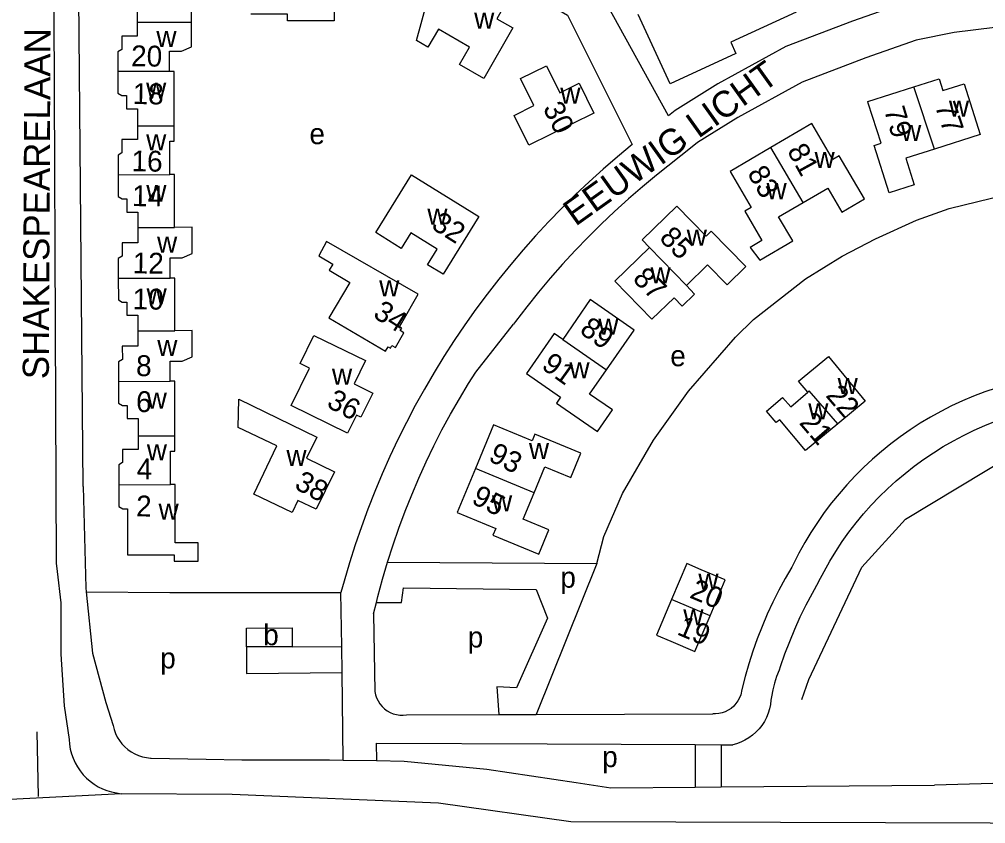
# Model space of a CAD drawing. Extents: x 159441 to 162086, y 388175 to 389787.
# Drawn here: x 161032.2 to 161217.5, y 388347.8 to 388501.9 of the extents above; entities that cross this region are included whole.
import ezdxf

# ---------------------------------------------------------------- set-up
doc = ezdxf.new("R2010")
doc.units = 0
for name, color, linetype in [('BLT_Basislijn', 7, 'Continuous'), ('BLT_Bebouwing', 7, 'Continuous'), ('BLT_Centroide', 7, 'Continuous'), ('BLT_Huisnummer', 7, 'Continuous'), ('BLT_Huisnummer_ tussenligend', 7, 'Continuous'), ('BLT_Onderverdeling_panden', 7, 'Continuous'), ('BLT_Straatnaam', 7, 'Continuous'), ('BLT_Vlakafsluiter', 7, 'Continuous')]:
    doc.layers.add(name, color=color, linetype=linetype)

msp = doc.modelspace()

# ---------------------------------------------------------------- linework, layer by layer
at = {"layer": 'BLT_Basislijn'}
for p, q in [((161044.45, 388412.36), (161043.5, 388520.52)), ((161156.97, 388489.54), (161150.84, 388502.85)), ((161181.14, 388503.3), (161168.61, 388497.54)), ((161168.61, 388497.54), (161169.61, 388495.36)), ((161169.61, 388495.36), (161156.97, 388489.54)), ((161161.23, 388477.48), (161154.41, 388472.07)), ((161119.72, 388434.3), (161126.93, 388443.46)), ((161102.8, 388397.85), (161142.94, 388397.62)), ((161142.94, 388397.62), (161131.31, 388368.69)), ((161045.04, 388392.19), (161061.04, 388392.06)), ((161061.04, 388392.06), (161068.06, 388392.06)), ((161068.06, 388392.06), (161093.88, 388392.06)), ((161094.02, 388381.72), (161093.88, 388392.06)), ((161100.15, 388387.99), (161100.67, 388390.13)), ((161100.15, 388387.99), (161100.38, 388373.11)), ((161075.75, 388381.62), (161075.75, 388376.55)), ((161084.54, 388381.63), (161094.02, 388381.72)), ((161094.08, 388376.72), (161094.02, 388381.72)), ((161075.75, 388376.55), (161094.08, 388376.72)), ((161094.29, 388359.95), (161094.08, 388376.72)), ((161106.47, 388368.61), (161124.14, 388368.67)), ((161124.14, 388368.67), (161131.31, 388368.69)), ((161131.31, 388368.69), (161165.19, 388368.78)), ((161035.9, 388352.97), (161035.64, 388365.37)), ((161100.63, 388363.17), (161100.72, 388359.84)), ((161100.63, 388363.17), (161133.4, 388363.02)), ((161133.4, 388363.02), (161161.8, 388362.9)), ((161161.8, 388362.9), (161166.8, 388362.88)), ((161161.8, 388362.9), (161161.8, 388354.77)), ((161166.8, 388362.88), (161166.8, 388354.81)), ((161166.8, 388362.88), (161169.01, 388362.87)), ((161057.5, 388360.31), (161068.06, 388360.12)), ((161094.29, 388359.95), (161100.72, 388359.84)), ((161161.8, 388354.77), (161166.8, 388354.81)), ((161166.8, 388354.81), (161207.68, 388355.15))]:
    msp.add_line(p, q, dxfattribs=at)
for points in [[(161038.68, 388533.55), (161039.27, 388397.68), (161039.46, 388396.05)], [(161106.86, 388520.45), (161137.31, 388502.69), (161149.7, 388477.9)], [(161209.96, 388506.74), (161202.16, 388505.14), (161191.95, 388501.56), (161179.18, 388496.71), (161166.15, 388489.55), (161157.98, 388484.44), (161156.67, 388483.44)], [(161156.67, 388483.44), (161144.86, 388504.81), (161145.34, 388505.05)], [(161252.46, 388501.23), (161231.19, 388501.83), (161211.46, 388499.39)], [(161211.46, 388499.39), (161204.16, 388497.89), (161194.52, 388494.52), (161182.33, 388489.88), (161169.95, 388483.08), (161162.26, 388478.27), (161161.23, 388477.48)], [(161149.7, 388477.9), (161146.9, 388475.58), (161144.14, 388473.21), (161141.45, 388470.77), (161138.8, 388468.27), (161136.21, 388465.72), (161133.68, 388463.11), (161131.2, 388460.44), (161128.79, 388457.72), (161126.43, 388454.95), (161124.14, 388452.13), (161121.91, 388449.25), (161119.74, 388446.33), (161117.64, 388443.36), (161115.6, 388440.35), (161113.63, 388437.29), (161111.73, 388434.19), (161109.89, 388431.05), (161108.13, 388427.87), (161106.43, 388424.65), (161104.81, 388421.4), (161103.26, 388418.11), (161101.78, 388414.78), (161100.38, 388411.43), (161099.05, 388408.04), (161097.79, 388404.63), (161096.61, 388401.19), (161095.51, 388397.72), (161094.48, 388394.23), (161093.88, 388392.06)], [(161154.41, 388472.07), (161151.68, 388469.8), (161148.99, 388467.48), (161146.35, 388465.09), (161143.77, 388462.65), (161141.25, 388460.15), (161138.78, 388457.59), (161136.37, 388454.98), (161134.02, 388452.31), (161131.73, 388449.59), (161129.5, 388446.82), (161127.34, 388444), (161126.93, 388443.46)], [(161142.94, 388397.62), (161144.27, 388402.76), (161147.83, 388411.06), (161153.81, 388421.28), (161160.51, 388430.62), (161169.5, 388441.01), (161173, 388444.35), (161182.93, 388452.15), (161189.95, 388456.49), (161196.34, 388459.87), (161204.24, 388463.4), (161210.47, 388465.66), (161223.83, 388468.92), (161234.58, 388469.87), (161249.06, 388469.87), (161261.63, 388468.97), (161276.91, 388466.53), (161314.68, 388462.2)], [(161102.8, 388397.85), (161103.86, 388401.18), (161104.98, 388404.41), (161106.17, 388407.62), (161107.44, 388410.8), (161108.79, 388413.96), (161110.2, 388417.07), (161111.69, 388420.16), (161113.25, 388423.21), (161114.88, 388426.22), (161116.58, 388429.19), (161118.35, 388432.12), (161119.72, 388434.3)], [(161219.48, 388431.24), (161217.31, 388430.5), (161215.17, 388429.67), (161213.05, 388428.78), (161210.97, 388427.81), (161208.92, 388426.77), (161206.91, 388425.66), (161204.94, 388424.48), (161203.01, 388423.23), (161201.13, 388421.91), (161199.3, 388420.53), (161197.51, 388419.09), (161195.77, 388417.58), (161194.09, 388416.02), (161192.47, 388414.4), (161190.9, 388412.72), (161189.39, 388410.99), (161187.94, 388409.21), (161186.55, 388407.38), (161185.23, 388405.5), (161183.98, 388403.57), (161182.79, 388401.61), (161181.67, 388399.6), (161180.63, 388397.56), (161180.32, 388396.92)], [(161185.47, 388394.09), (161186.5, 388396.08), (161187.59, 388398.03), (161188.75, 388399.93), (161189.98, 388401.8), (161191.28, 388403.61), (161192.64, 388405.39), (161194.06, 388407.11), (161195.55, 388408.78), (161197.09, 388410.39), (161198.69, 388411.95), (161200.35, 388413.45), (161202.05, 388414.89), (161203.81, 388416.27), (161205.62, 388417.59), (161207.47, 388418.84), (161209.36, 388420.02), (161211.3, 388421.13), (161213.27, 388422.17), (161215.29, 388423.15), (161217.33, 388424.05), (161219.41, 388424.87)], [(161182.22, 388371.55), (161183.56, 388375.39), (161193.75, 388396.9), (161202.14, 388406.08), (161222.4, 388418.29), (161232.89, 388422.06), (161242.43, 388423.36), (161250.05, 388422.72), (161287.09, 388418.41), (161290.39, 388417.22), (161292.6, 388414.97), (161293.51, 388411.95), (161294.09, 388393.96)], [(161044.45, 388412.36), (161044.96, 388392.95), (161045.04, 388392.19)], [(161310.31, 388401.34), (161304.94, 388397.76), (161302.38, 388393.16), (161297.78, 388384.47), (161294.21, 388377.06), (161290.88, 388369.39), (161288.33, 388365.05), (161287.82, 388362.74), (161286.54, 388361.21), (161283.21, 388358.4), (161276.57, 388357.63), (161259.19, 388356.61), (161207.68, 388355.15)], [(161100.67, 388390.13), (161100.96, 388391.32), (161101.85, 388394.63), (161102.8, 388397.85)], [(161180.32, 388396.92), (161179.04, 388394.72), (161177.82, 388392.49), (161176.68, 388390.22), (161175.61, 388387.91), (161174.61, 388385.57), (161173.69, 388383.2), (161172.84, 388380.8), (161172.07, 388378.38), (161171.37, 388375.93), (161170.76, 388373.47), (161170.53, 388372.47)], [(161039.46, 388396.05), (161040.17, 388390.05), (161040.17, 388380.22), (161040.82, 388370.32), (161041.76, 388363.9)], [(161185.47, 388394.09), (161184.21, 388391.87), (161183.01, 388389.61), (161181.88, 388387.32), (161180.83, 388384.99), (161179.85, 388382.62), (161178.94, 388380.23), (161178.11, 388377.81), (161177.91, 388377.18)], [(161045.04, 388392.19), (161046.24, 388380.43), (161048.8, 388370.98), (161050.2, 388366.55)], [(161100.67, 388390.13), (161105.48, 388390.16), (161105.89, 388392.94), (161131.32, 388392.61), (161133.46, 388387.14), (161127.56, 388373.78), (161123.79, 388373.95), (161124.14, 388368.67)], [(161177.91, 388377.18), (161177.42, 388375.93), (161177.01, 388374.66), (161176.68, 388373.37), (161176.42, 388372.06), (161176.33, 388371.44)], [(161100.38, 388373.11), (161100.5, 388372.47), (161100.71, 388371.85), (161100.99, 388371.27), (161101.33, 388370.72), (161101.75, 388370.22), (161102.22, 388369.77), (161102.74, 388369.39), (161103.31, 388369.07), (161103.91, 388368.82), (161104.54, 388368.65), (161105.18, 388368.56), (161105.83, 388368.54), (161106.47, 388368.61)], [(161170.53, 388372.47), (161170.3, 388371.86), (161169.99, 388371.29), (161169.62, 388370.76), (161169.18, 388370.28), (161168.69, 388369.85), (161168.15, 388369.49), (161167.57, 388369.2), (161166.96, 388368.98), (161166.33, 388368.84), (161165.68, 388368.78), (161165.19, 388368.78)], [(161176.33, 388371.44), (161176.23, 388370.58), (161176.05, 388369.73), (161175.79, 388368.9), (161175.46, 388368.09), (161175.06, 388367.32), (161174.58, 388366.59), (161174.05, 388365.9), (161173.45, 388365.27), (161172.79, 388364.7), (161172.09, 388364.19), (161171.34, 388363.74), (161170.55, 388363.37), (161169.74, 388363.07), (161169.01, 388362.87)], [(161050.2, 388366.55), (161050.39, 388365.79), (161050.66, 388365.05), (161050.99, 388364.34), (161051.4, 388363.67), (161051.88, 388363.05), (161052.42, 388362.47), (161053.01, 388361.96), (161053.65, 388361.5), (161054.33, 388361.12), (161055.05, 388360.8), (161055.8, 388360.57), (161056.57, 388360.4), (161057.35, 388360.32), (161057.5, 388360.31)], [(161041.76, 388363.9), (161041.83, 388362.97), (161041.98, 388362.06), (161042.21, 388361.16), (161042.51, 388360.29), (161042.89, 388359.44), (161043.34, 388358.63), (161043.86, 388357.86), (161044.45, 388357.14), (161045.09, 388356.48), (161045.79, 388355.87), (161046.53, 388355.32), (161047.33, 388354.84), (161048.16, 388354.43), (161049.02, 388354.09), (161049.91, 388353.83), (161050.82, 388353.65), (161051.74, 388353.47)], [(161068.06, 388360.12), (161074.85, 388360), (161091.71, 388360), (161094.29, 388359.95)], [(161100.72, 388359.84), (161106.01, 388359.74), (161121.85, 388358.21), (161138.96, 388355.66), (161145.61, 388354.63), (161161.8, 388354.77)], [(161300.85, 388350.22), (161285.77, 388350.48), (161269.67, 388349.71), (161253.82, 388348.43), (161238.49, 388347.75), (161137.94, 388348.07), (161112.58, 388351.71), (161072.99, 388353.31), (161051.74, 388353.47)]]:
    msp.add_lwpolyline(points, dxfattribs=at)
at = {"layer": 'BLT_Bebouwing'}
for p, q in [((161054.82, 388501.29), (161054.83, 388500)), ((161184.17, 388481.95), (161176.33, 388477.36)), ((161153.04, 388458.2), (161153.03, 388458.2)), ((161141.69, 388448.18), (161136.39, 388440.54)), ((161123.13, 388424.2), (161119.66, 388415.81)), ((161075.75, 388381.62), (161075.74, 388385.21)), ((161084.54, 388381.63), (161075.75, 388381.62))]:
    msp.add_line(p, q, dxfattribs=at)
for points in [[(161051.06, 388511.52), (161051.07, 388507.53), (161051.82, 388507.09), (161052.72, 388507.09), (161052.72, 388504.57), (161054.82, 388504.58), (161054.82, 388501.29)], [(161065.22, 388501.31), (161065.2, 388506.92), (161063.29, 388507.49), (161061.88, 388507.49), (161061.87, 388511.73), (161060.97, 388511.72)], [(161115.81, 388510.66), (161123.13, 388506.48), (161123.43, 388506.89), (161125.78, 388505.59), (161123.76, 388502.03), (161126.81, 388500.29), (161121.27, 388490.57), (161116.61, 388493.23), (161118.51, 388496.56), (161112.56, 388500), (161110.56, 388496.57), (161108.38, 388497.83), (161110.33, 388505.09), (161113.62, 388504.21), (161114.17, 388505.18), (161113.02, 388505.84), (161115.81, 388510.66)], [(161092.59, 388503.26), (161092.59, 388501.63), (161083.62, 388501.6), (161083.61, 388502.91), (161076.63, 388502.89)], [(161061.02, 388491.93), (161061.01, 388495.79), (161063.31, 388495.79), (161065.23, 388496.65), (161065.22, 388501.31)], [(161054.83, 388500), (161054.83, 388498.66), (161051.84, 388498.66), (161051.84, 388496.12), (161051.1, 388495.67), (161051.11, 388491.9)], [(161051.11, 388491.9), (161051.12, 388487.73), (161051.87, 388487.28), (161052.77, 388487.28), (161052.77, 388484.77), (161054.87, 388484.77), (161054.88, 388481.49)], [(161061.92, 388481.5), (161061.93, 388491.93), (161061.02, 388491.93)], [(161127.07, 388483.5), (161130.87, 388485.37), (161128.3, 388490.58), (161133.26, 388493.02), (161135.82, 388487.81), (161139.56, 388489.65), (161142.37, 388483.95), (161129.88, 388477.79), (161127.07, 388483.5)], [(161203.75, 388489), (161208.57, 388490.53), (161209.3, 388488.27), (161213.34, 388489.55), (161216.42, 388479.81), (161207.66, 388477.02)], [(161207.66, 388477.02), (161202.19, 388475.28), (161203.81, 388470.18), (161199.01, 388468.65), (161196.11, 388477.74), (161197.44, 388478.17), (161194.99, 388485.83), (161194.89, 388486.19), (161203.75, 388489)], [(161054.88, 388481.49), (161054.88, 388478.87), (161051.89, 388478.86), (161051.89, 388476.34), (161051.14, 388475.89), (161051.15, 388472.11)], [(161061.08, 388472.14), (161061.06, 388478.55), (161061.92, 388478.55), (161061.92, 388481.5)], [(161182.49, 388466.82), (161187.2, 388469.57), (161189.9, 388464.95), (161194.25, 388467.5), (161189.43, 388475.75), (161188.21, 388475.04), (161184.17, 388481.95)], [(161176.33, 388477.36), (161168.48, 388472.77), (161172.52, 388465.85), (161171.31, 388465.14), (161174.6, 388459.51), (161172.34, 388458.18), (161174.2, 388455.78), (161180.49, 388459.45), (161177.79, 388464.07), (161182.49, 388466.82)], [(161051.15, 388472.11), (161051.15, 388467.95), (161051.9, 388467.5), (161052.8, 388467.5), (161052.81, 388464.97), (161054.91, 388464.97), (161054.91, 388462.02)], [(161061.97, 388462.04), (161061.98, 388472.14), (161061.08, 388472.14)], [(161107.4, 388472.08), (161120.31, 388464.1), (161113.48, 388453.05), (161110.5, 388454.87), (161112.34, 388457.83), (161107.28, 388460.97), (161105.45, 388458), (161100.57, 388461.03), (161107.4, 388472.08)], [(161158.29, 388466.13), (161151.64, 388459.64), (161153.04, 388458.2)], [(161160.11, 388450.87), (161164.17, 388454.83), (161167.91, 388450.99), (161171.52, 388454.51), (161164.87, 388461.32), (161163.9, 388460.37), (161158.29, 388466.13)], [(161054.91, 388462.02), (161054.91, 388459.06), (161051.92, 388459.06), (161051.92, 388456.53), (161051.18, 388456.08), (161051.19, 388452.3)], [(161061.12, 388452.33), (161061.11, 388456.19), (161063.42, 388456.19), (161065.33, 388457.05), (161065.32, 388462.05), (161061.97, 388462.04)], [(161091.1, 388459.3), (161089.64, 388456.59), (161092.34, 388455.01), (161091.63, 388453.81), (161095.55, 388451.5), (161091.55, 388444.69), (161102.42, 388438.33), (161102.91, 388439.16), (161103.38, 388438.91), (161103.65, 388439.37), (161104.34, 388438.99), (161105.94, 388441.85), (161105.25, 388442.25), (161105.57, 388442.71), (161105.1, 388442.98), (161105.56, 388443.71), (161108.69, 388449.23), (161091.1, 388459.3)], [(161153.03, 388458.2), (161146.37, 388451.7), (161153.49, 388444.41), (161157.76, 388448.56), (161159.32, 388446.95), (161161.68, 388449.25), (161160.11, 388450.87)], [(161051.19, 388452.3), (161051.2, 388448.14), (161051.95, 388447.69), (161052.85, 388447.69), (161052.85, 388445.18), (161054.95, 388445.18), (161054.95, 388442.22)], [(161062, 388442.23), (161062.02, 388452.33), (161061.12, 388452.33)], [(161144.77, 388434.73), (161150.07, 388442.36), (161141.69, 388448.18)], [(161054.95, 388442.22), (161054.96, 388439.27), (161051.96, 388439.26), (161051.97, 388436.74), (161051.23, 388436.29), (161051.24, 388432.51)], [(161061.15, 388432.53), (161061.14, 388436.38), (161063.45, 388436.38), (161065.36, 388437.23), (161065.35, 388442.24), (161062, 388442.23)], [(161136.39, 388440.54), (161134.75, 388441.68), (161129.45, 388434.03), (161136, 388429.48), (161135.2, 388428.33), (161143.04, 388422.89), (161145.92, 388427.04), (161141.53, 388430.08), (161144.77, 388434.73)], [(161088.65, 388441.34), (161098.57, 388436.53), (161096.4, 388432.04), (161099.98, 388430.29), (161097.72, 388425.63), (161096.83, 388426.05), (161095.15, 388422.62), (161084.34, 388427.9), (161087.83, 388435.05), (161086.03, 388435.92), (161088.65, 388441.34)], [(161183.4, 388430.45), (161181.62, 388432.53), (161187.39, 388437.27), (161194.38, 388428.73), (161189.13, 388424.4)], [(161051.24, 388432.51), (161051.24, 388428.35), (161051.99, 388427.9), (161052.89, 388427.91), (161052.9, 388425.38), (161055, 388425.38), (161055, 388422.09)], [(161062.04, 388422.1), (161062.05, 388432.53), (161061.15, 388432.53)], [(161189.13, 388424.4), (161182.93, 388419.28), (161178, 388425.17), (161177.33, 388424.61), (161175.48, 388426.83), (161178.54, 388429.45), (161180.11, 388427.63), (161183.4, 388430.45)], [(161074.32, 388429.12), (161089.24, 388421.85), (161087.28, 388417.79), (161092.63, 388415.19), (161089.15, 388408), (161085.61, 388409.71), (161084.51, 388407.4), (161077.19, 388410.9), (161081.61, 388420.17), (161074.2, 388423.71), (161074.32, 388429.12)], [(161130.91, 388411.13), (161133, 388416.17), (161137.96, 388414.11), (161139.89, 388418.78), (161131.07, 388422.43), (161130.53, 388421.13), (161123.13, 388424.2)], [(161055, 388422.09), (161055.01, 388419.48), (161052.01, 388419.47), (161052.01, 388416.95), (161051.27, 388416.5), (161051.28, 388412.71)], [(161061.18, 388412.73), (161061.17, 388419.17), (161062.04, 388419.17), (161062.04, 388422.1)], [(161119.66, 388415.81), (161116.18, 388407.41), (161123.56, 388404.35), (161123.01, 388403.03), (161131.82, 388399.37), (161133.76, 388404.05), (161128.82, 388406.09), (161130.91, 388411.13)], [(161051.28, 388412.71), (161051.28, 388408.56), (161052.03, 388408.11), (161052.93, 388408.11), (161052.93, 388399.28), (161061.93, 388399.28)], [(161061.93, 388399.28), (161061.93, 388398.08), (161066.53, 388398.08), (161066.53, 388401.58), (161062.07, 388401.58), (161062.08, 388412.73), (161061.18, 388412.73)], [(161164.65, 388387.61), (161167.55, 388394.47), (161162.95, 388396.42), (161160.18, 388397.59), (161157.28, 388390.74)], [(161157.28, 388390.74), (161154.37, 388383.88), (161157.13, 388382.71), (161161.74, 388380.76), (161164.65, 388387.61)], [(161075.74, 388385.21), (161084.5, 388385.26), (161084.54, 388381.63)]]:
    msp.add_lwpolyline(points, dxfattribs=at)
at = {"layer": 'BLT_Onderverdeling_panden'}
for p, q in [((161065.22, 388501.31), (161054.82, 388501.29)), ((161061.02, 388491.93), (161051.11, 388491.9)), ((161207.66, 388477.02), (161203.75, 388489)), ((161054.88, 388481.49), (161061.92, 388481.5)), ((161182.49, 388466.82), (161176.33, 388477.36)), ((161051.15, 388472.11), (161061.08, 388472.14)), ((161054.91, 388462.02), (161061.97, 388462.04)), ((161153.03, 388458.2), (161160.11, 388450.87)), ((161051.19, 388452.3), (161061.12, 388452.33)), ((161054.95, 388442.22), (161062, 388442.23)), ((161136.39, 388440.54), (161144.77, 388434.73)), ((161051.24, 388432.51), (161061.15, 388432.53)), ((161055, 388422.09), (161062.04, 388422.1)), ((161130.91, 388411.13), (161119.66, 388415.81)), ((161051.28, 388412.71), (161061.18, 388412.73)), ((161164.65, 388387.61), (161157.28, 388390.74))]:
    msp.add_line(p, q, dxfattribs=at)
msp.add_lwpolyline([(161189.13, 388424.4), (161183.67, 388430.69), (161183.4, 388430.45)], dxfattribs=at)
at = {"layer": 'BLT_Vlakafsluiter'}
msp.add_lwpolyline([(161051.74, 388353.47), (161019.17, 388351.81)], dxfattribs=at)

# ---------------------------------------------------------------- texts
at = {"layer": 'BLT_Centroide'}
for s, p in [('w', (161119.42, 388500.11)), ('w', (161058.49, 388496.59)), ('w', (161056.52, 388486.7)), ('w', (161135.94, 388485.72)), ('w', (161210.45, 388483.27)), ('e', (161087.83, 388477.98)), ('w', (161201.28, 388478.59)), ('w', (161056.53, 388476.81)), ('w', (161184.69, 388473.44)), ('w', (161056.56, 388467.08)), ('w', (161175.48, 388467.44)), ('w', (161110.44, 388462.56)), ('w', (161058.62, 388457.19)), ('w', (161160.18, 388458.5)), ('w', (161153.23, 388451.31)), ('w', (161101.21, 388448.81)), ('w', (161056.61, 388447.27)), ('w', (161143.23, 388441.47)), ('w', (161058.66, 388437.38)), ('e', (161157.02, 388435.42)), ('w', (161137.69, 388433.12)), ('w', (161092.16, 388431.86)), ('w', (161189.11, 388430.09)), ('w', (161056.64, 388427.31)), ('w', (161183.48, 388425.25)), ('w', (161056.66, 388417.41)), ('w', (161083.42, 388416.31)), ('w', (161129.92, 388417.66)), ('w', (161122.84, 388407.59)), ('w', (161058.91, 388406)), ('p', (161135.95, 388392.97)), ('w', (161162.41, 388392.59)), ('w', (161159.52, 388385.75)), ('b', (161078.98, 388381.95)), ('p', (161118.2, 388381.51)), ('p', (161059.23, 388377.49)), ('p', (161143.97, 388358.58))]:
    msp.add_text(s, height=4, dxfattribs=at).set_placement(p)
at = {"layer": 'BLT_Huisnummer'}
for s, rotation, p in [('18', 359.1344, (161053.93, 388485.68)), ('30', 296.641, (161132.52, 388484.9)), ('77', 288.5788, (161207.71, 388485.32)), ('79', 286.5789, (161197.97, 388484.55)), ('81', 298.8966, (161179.34, 388476.73)), ('83', 299.8966, (161171.7, 388472.43)), ('14', 359.1344, (161053.81, 388466.12)), ('32', 327.8482, (161111, 388461.93)), ('85', 314.9878, (161154.74, 388459.8)), ('87', 314.9878, (161149.63, 388451.99)), ('10', 359.1344, (161053.92, 388446.34)), ('34', 327.8482, (161099.83, 388444.92)), ('89', 324.2782, (161139.44, 388441.92)), ('91', 324.2782, (161132.13, 388435.1)), ('6', 359.1344, (161054.57, 388426.66)), ('36', 331.8858, (161090.93, 388427.73)), ('22', 310.7007, (161186.68, 388429.73)), ('21', 310.7007, (161181.59, 388424.51)), ('93', 332.9852, (161121.95, 388417.42)), ('38', 331.8858, (161084.75, 388412.08)), ('95', 332.9852, (161118.69, 388409.27)), ('2', 359.1344, (161054.58, 388406.65)), ('20', 337.072, (161160.53, 388391.14)), ('19', 337.072, (161158.12, 388384.08))]:
    msp.add_text(s, height=4, rotation=rotation, dxfattribs=at).set_placement(p)
at = {"layer": 'BLT_Huisnummer_ tussenligend'}
for s, p in [('20', (161053.63, 388492.92)), ('16', (161053.7, 388472.79)), ('12', (161053.93, 388453.23)), ('8', (161054.57, 388433.55)), ('4', (161054.68, 388413.77))]:
    msp.add_text(s, height=4, rotation=359.1344, dxfattribs=at).set_placement(p)
at = {"layer": 'BLT_Straatnaam'}
for s, rotation, p in [('SHAKESPEARELAAN', 89.712, (161037.86, 388432.93)), ('EEUWIG LICHT', 35.5606, (161138.85, 388462.12))]:
    msp.add_text(s, height=5, rotation=rotation, dxfattribs=at).set_placement(p)

doc.saveas('drawing.dxf')
